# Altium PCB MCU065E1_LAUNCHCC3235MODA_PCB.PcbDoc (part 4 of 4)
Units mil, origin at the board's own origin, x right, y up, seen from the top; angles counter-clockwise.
Board outline 2300 x 4280 mil, 4 copper layers (TOP, GND, PWR, BOTTOM), stack 62 mil thick; 300 components, 199 nets, 970 pads, 475 vias.
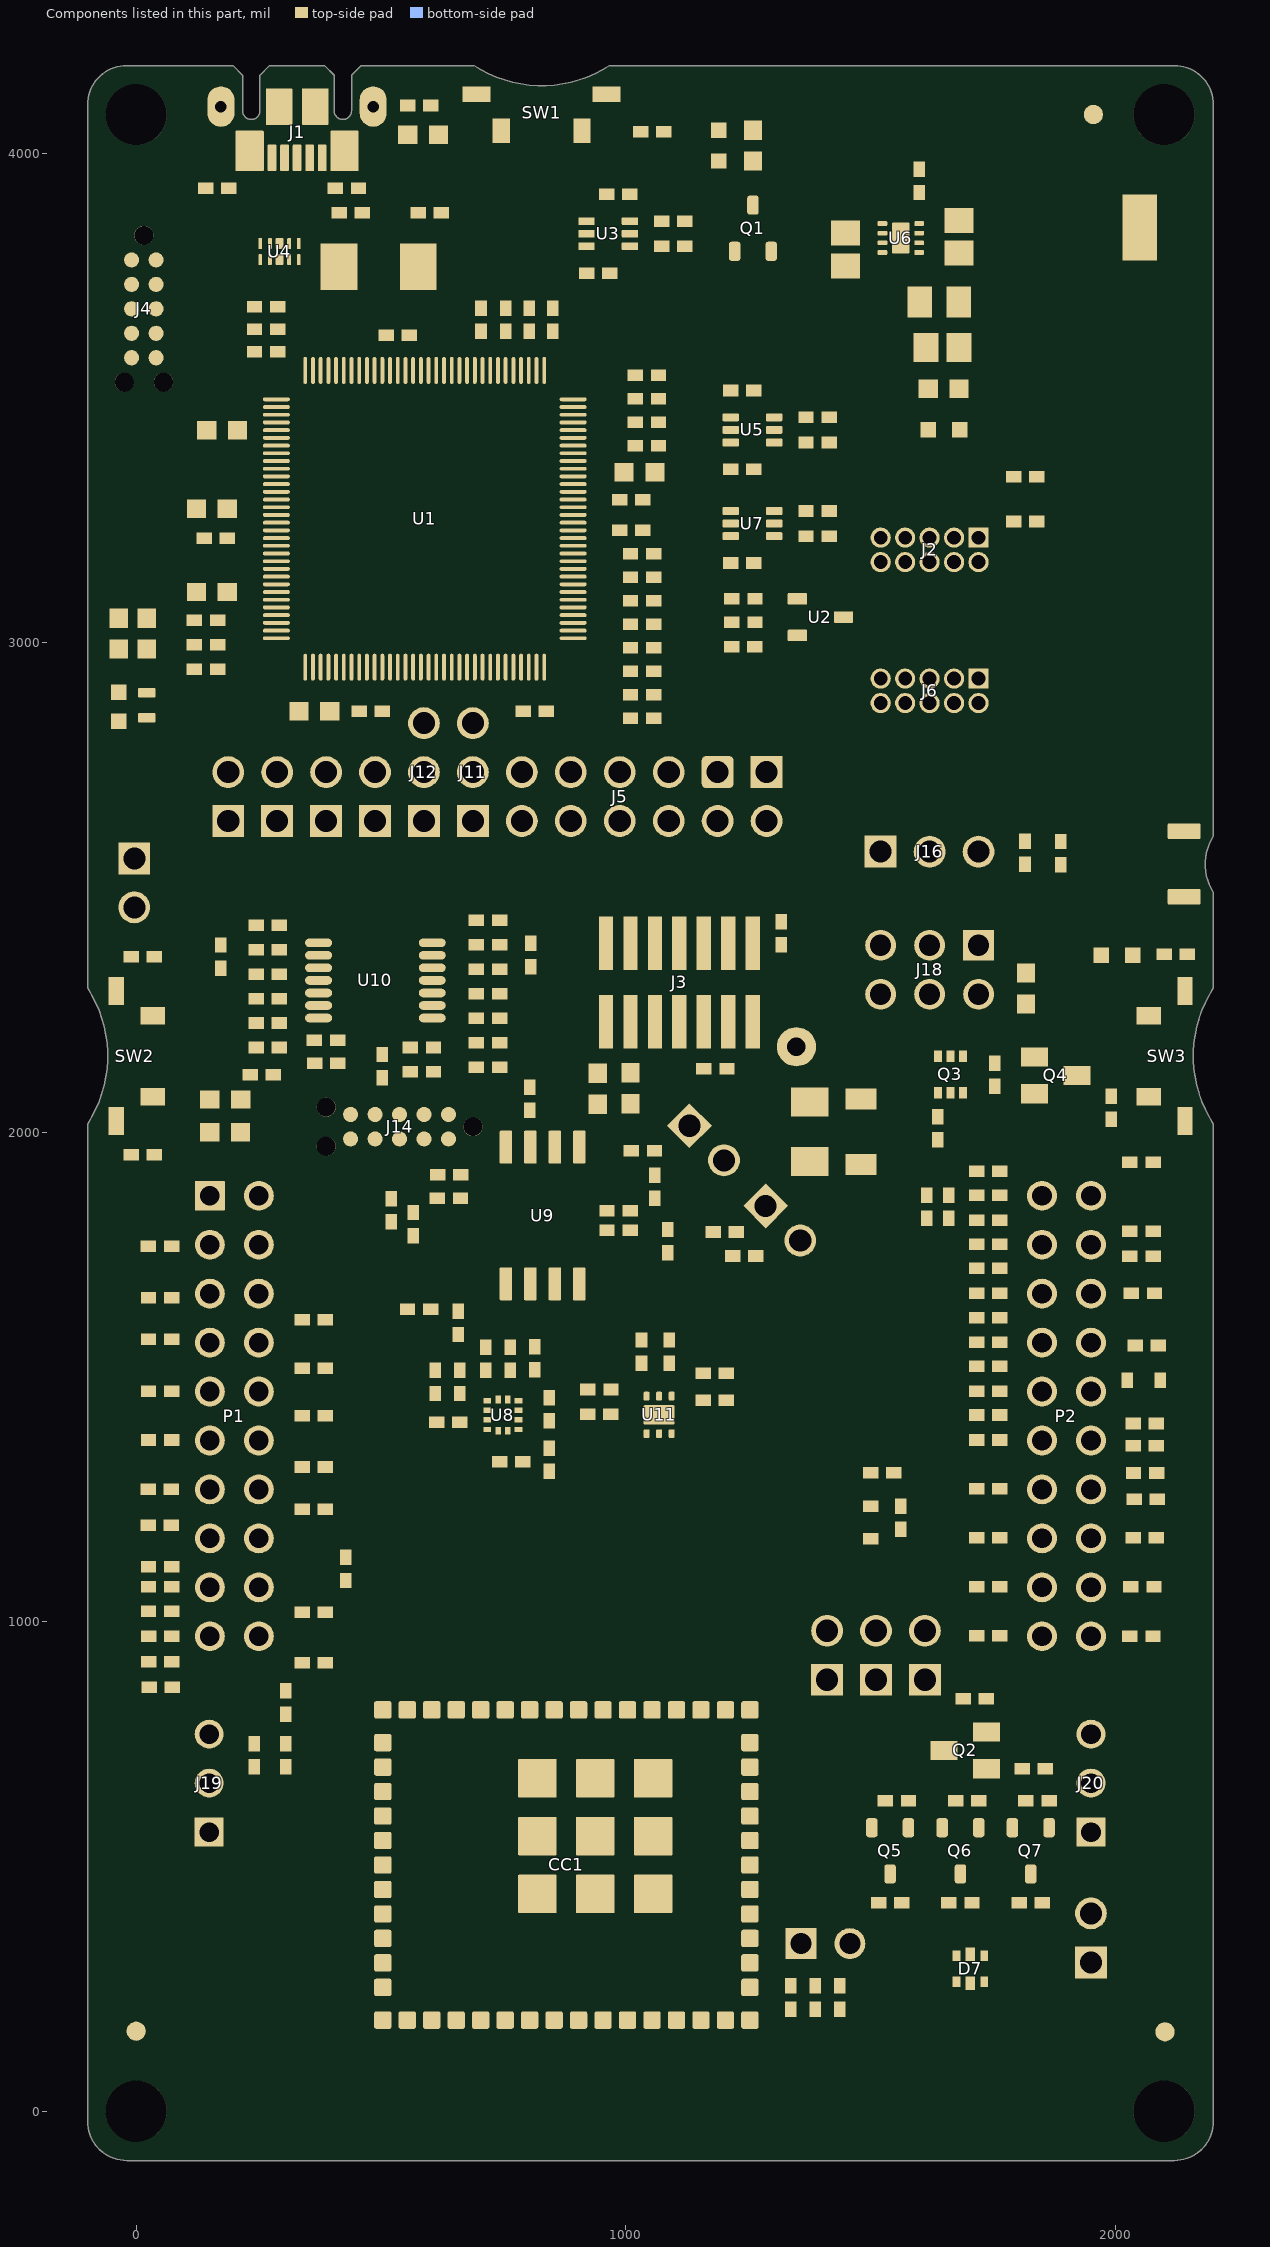
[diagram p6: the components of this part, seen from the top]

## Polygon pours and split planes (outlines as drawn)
no net on M4 3D STEP Bottom "M4 3D STEP Bottom-No Net" (solid, pour order 341): 2155.79,401.26 ccw(c2095.79,401.26) 2095.79,461.26 ccw(c2095.79,401.26) 2035.79,401.26 ccw(c2095.79,401.26) 2095.79,341.26 ccw(c2095.79,401.26) 2155.79,401.26
no net on M4 3D STEP Bottom "M4 3D STEP Bottom-No Net" (solid, pour order 342): 60.79,366.26 ccw(c0.79,366.26) 0.79,426.26 ccw(c0.79,366.26) -59.21,366.26 ccw(c0.79,366.26) 0.79,306.26 ccw(c0.79,366.26) 60.79,366.26
no net on M4 3D STEP Bottom "M4 3D STEP Bottom-No Net" (solid, pour order 340): 2015.79,3726.26 ccw(c1955.79,3726.26) 1955.79,3786.26 ccw(c1955.79,3726.26) 1895.79,3726.26 ccw(c1955.79,3726.26) 1955.79,3666.26 ccw(c1955.79,3726.26) 2015.79,3726.26
GND on TOP "GND_L01_P327" (solid, remove dead copper, pour order 327): -99.1,-100.74 2203.8,-100.74 2203.8,4117.38 2138.8,4182.38 -47.5,4182.38 -99.1,4130.78
VBUS_USB1 on TOP "L3 Signal-No Net" (solid, pour order 325): 1534.45,3807.43 1391.7,3807.43 1378.25,3820.88 1378.25,3883.02 1398.45,3903.22 1480.79,3903.22 1490.45,3893.57 1490.45,3851.56 1495.39,3846.61 1537.4,3846.61 1541.12,3842.89 1541.12,3814.11
VCC_LDO_3V3 on TOP "L3 Signal-No Net" (solid, remove dead copper, pour order 326): 1669.88,3489.43 1728.7,3489.43 1751.99,3512.73 1751.99,3810.28 1735.84,3826.44 1615.61,3826.44 1612.61,3823.43 1612.61,3799.01 1654.29,3757.33 1654.29,3505.03
GND on BOTTOM "GND_L04_P339" (solid, remove dead copper, pour order 339): -99.1,-100.74 2203.8,-100.74 2203.8,4117.38 2138.8,4182.38 -47.5,4182.38 -97.5,4132.38 -97.5,4124.08 -99.1,4132.38
VCC_BRD on BOTTOM "VCC_BRD_L04_P337" (solid, remove dead copper, pour order 337): 2057.55,2644.15 2088.64,2675.25 2088.64,3228.53 1920.48,3396.7 1837.19,3396.7 1812.21,3396.7 1790.73,3375.22 1790.73,3177.95 1881.36,3087.32 1881.36,2987.13 1720.25,2826.02 1389,2826.02 1232.05,2669.06 1232.05,2551.64 1326.07,2457.61 1871.01,2457.61
VBUS_USB1 on BOTTOM "VBUS_USB1_L04_P338" (solid, remove dead copper, pour order 338): 51.88,2994.75 70.47,2976.16 125.75,2976.16 229.68,2872.23 229.68,2698.8 247.53,2680.94 406.96,2680.94 406.96,2683.58 439.86,2716.48 439.86,2904.48 406.96,2937.38 406.96,3312.96 527.47,3433.47 846.63,3433.48 1109.11,3695.97 1376.48,3695.97 1493.72,3813.21 1493.72,3918.79 1368.78,4043.73 1163.57,4043.73 1107.39,3987.54 606.61,3987.54 128.57,3987.54 79,3937.98 79,3746.2 172.95,3652.26 172.95,3503.67 51.88,3382.6
VCC_LDO_3V3 on PWR "PWR-No Net 3" (solid, remove dead copper, pour order 336): -99.21,4188.01 2200.79,4188.01 2200.79,2650.8 -99.21,2650.8
VCC_BRD on PWR "PWR-No Net 2" (solid, remove dead copper, pour order 335): -70.85,2651.9 384.52,2651.9 378.6,2329.9 253,2204.3 253,1970.21 1429,1677.24 1429,1234.2 1409.8,978.7 1409.8,711.6 1409.8,608.7 1107.3,306.2 -96.59,306.2 -100.43,1408.72 -99.21,1708.3 -70.85,1825.15
VBAT_CC on PWR "PWR-No Net 1" (solid, remove dead copper, pour order 334): 1049.92,1711.49 1049.93,1768.6 1015.38,1803.15 237.06,2010.16 237.06,2668.65 1542.9,2668.64 1856.72,2297.02 1856.72,438.3 1674.62,438.3 1654.56,293.87 1388.14,272.26 1397.77,595.55 1419.98,1341.44
GND on PWR "GND_L03_P332" (solid, remove dead copper, pour order 332): 431.08,524.74 572.16,524.74 777.95,730.53 1403.16,730.53 1403.16,289.92 1649.27,289.92 1661.9,-81.9 1664.1,-84.1 1647.46,-100.74 -103.82,-100.74 -92.13,326.1 227.01,320.67
VCC_BRD on PWR "VCC_BRD_L03_P333" (solid, remove dead copper, pour order 333): 1614.61,1945.17 1598.72,1945.17 1575.31,1968.59 1575.31,2002.44 1614.61,2041.74 1614.61,2606.59 1572.12,2649.08 1472.7,2649.08 1342.43,2518.81 582.21,2518.82 536.84,2564.19 536.84,2669.42 528.87,2677.39 433.73,2677.39 403.3,2646.96 403.3,2461.78 384.05,2442.53 -70.59,2434.92 -70.59,2796.96 2200.79,2796.96 2200.79,1257.1 1865.7,1257.1 1865.7,1738.81 1614.61,1944.64
GND on PWR "GND_L03_P330" (solid, remove dead copper, pour order 330): 2107.5,1195.1 2061.5,1257.2 1856.4,1269.2 1856.4,565.53 1733.27,442.4 1684.9,442.4 1667,424.4 1500.1,257.5 1500.1,-96.92 1776.99,-79.41 1786.17,-6.81 1989.6,165.08 1989.6,286.1 2072.85,369.35 2107.5,896.54
VCC_BRD on PWR "VCC_BRD_L03_P329" (solid, remove dead copper, pour order 329): 1656.35,163.28 1656.35,237.76 1758.3,339.7 1808.45,339.7 2067.6,598.84 2067.6,1280.1 2056.8,1290.9 2203.8,1291.9 2203.8,-75.9 2207.8,-79.9 2204.8,-82.9 1656.34,-82.9
VCC_BUFFER on PWR "L3 Signal-No Net" (solid, remove dead copper, pour order 331): 1323.98,2943.63 1235.06,2854.7 1235.06,2815.65 1263.98,2786.73 1381.62,2786.73 1483.34,2888.45 1483.34,2939.26 1516.43,2972.35 1664.3,2972.35 1730.31,2972.35 1838.04,3080.09 1838.04,3168.38 1808.5,3197.92 1808.5,3283.36 1570.69,3521.17 1570.69,3766.03 1373.14,3963.58 1163.65,3963.58 1033.35,3833.28 1033.35,3673.64 1153.72,3553.27 1153.72,3421.02 1189.35,3385.38 1272.5,3385.38 1323.98,3333.91
GND on GND "GND_L02_P328" (solid, remove dead copper, pour order 328): -99.1,-100.74 2203.8,-100.74 2203.8,4117.38 2138.8,4182.38 -47.5,4182.38 -97.5,4132.38 -97.5,4124.08 -99.1,4132.38

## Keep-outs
Keep-Out Layer:
  circle w1: c15.79,3832.26 r32
  circle w1: c55.79,3532.26 r30
  circle w1: c-24.21,3532.26 r30
  circle w1: c0,163.48 r60
  circle w1: c2101.9,162.18 r60
  circle w1: c2101.57,-1.52 r79.5
  circle w1: c388.2,1971.38 r30
  circle w1: c388.2,2051.38 r30
  circle w1: c688.2,2011.38 r32
  circle w1: c0,-1.52 r79.5
  circle w1: c1955.64,4079.33 r60
  lines w1: 222.28,-97.58 222.28,-83 -20,-83 cw(c-20,-20) -83,-20 -83,2017.29 -82.21,2018.08 ccw(c-302.14,2156.76) -82.21,2295.45 -83,2296.24 -83,4098.53 cw(c-20,4098.53) -20,4161.53 197.88,4161.53 207.57,4151.84 207.57,4069.01 ccw(c235.28,4081.93) 263,4069.01 263,4151.84 272.68,4161.53 384.89,4161.53 394.57,4151.84 394.57,4069.01 ccw(c422.29,4081.93) 450.01,4069.01 450.01,4151.84 459.69,4161.53 689.5,4161.53 ccw(c828.09,4381.51) 966.75,4161.57 ; 780.99,-97.58 780.99,-83 2120,-83 ccw(c2120,-20) 2183,-20 2183,2017.26 ; 966.77,4161.53 2120,4161.53 ; 1383.58,4161.53 2120,4161.53 ; 2183.06,2017.26 cw(c2402.98,2155.95) 2183,2294.54 2182.99,2483.26 2121,2483.26 2121,2611.26 2183,2611.26 2183,4098.53 ccw(c2120,4098.53) 2120,4161.53

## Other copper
TOP:
  pour cut-out: 622.3,144.68 618.71,136.98 691.76,136.98 686.21,144.68
  pour cut-out: 173.93,3405.65 177.55,3405.65 179.55,3407.65 179.55,3461.05 177.55,3463.05 173.93,3463.05
  pour cut-out: 153.05,3302.19 156.68,3302.19 158.68,3300.19 158.68,3246.79 156.68,3244.79 153.05,3244.79
  pour cut-out: 153.05,3132.34 156.68,3132.34 158.68,3130.34 158.68,3076.94 156.68,3074.94 153.05,3074.94
  pour cut-out: 45.42,2881.04 45.42,2863.58 -61.23,2863.58 -61.23,2875.14 -20.37,2875.14 -14.47,2881.04
  pour cut-out: 361.88,2831.4 368.81,2831.4 368.81,2879.59 361.88,2879.59
  pour cut-out: 50.37,3020.34 -63.83,3020.34 -63.83,3016.37 -62.18,3014.72 48.37,3014.72 50.37,3016.72
  pour cut-out: -99.21,136.98 2200.79,136.98 2200.79,-99.62 -99.21,-99.62
  pour cut-out: 686.21,236.99 686.21,144.68 621.66,144.68 621.66,236.91
  text ".layer_Name" at -465.21,-1154.21 h60
GND:
  pour cut-out: 979.65,2784.19 979.65,2773.17 981.26,2771.56 993.17,2771.56 994.18,2772.57 994.18,2783.18 991.44,2785.92 981.38,2785.92
  pour cut-out: 1096.58,3469.94 1096.58,3529.33 1099.49,3532.25 1105.33,3532.25 1108.41,3529.17 1108.41,3469.16 1105.79,3466.54 1099.98,3466.54
  pour cut-out: -99.21,136.98 2200.79,136.98 2200.79,-99.62 -99.21,-99.62
  text ".layer_Name" at -465.21,-1154.21 h60
PWR:
  pour cut-out: 355.99,2432.31 355.99,2413.97 363.04,2413.97 364.21,2415.14 364.21,2431.11 363.01,2432.31
  pour cut-out: -99.21,136.98 2200.79,136.98 2200.79,-99.62 -99.21,-99.62
  text ".layer_Name" at -465.21,-1154.21 h60
BOTTOM:
  region net SOP0: 788.75,257.91
  pour cut-out: 1096.58,3469.94 1096.58,3529.33 1099.49,3532.25 1105.33,3532.25 1108.41,3529.17 1108.41,3469.16 1105.79,3466.54 1099.98,3466.54
  pour cut-out: 773.96,3727.62 833.35,3727.62 836.26,3724.7 836.26,3718.87 833.18,3715.79 773.17,3715.79 770.55,3718.41 770.55,3724.22
  pour cut-out: 1080.79,3131.86 1080.79,3111.42 1088.9,3103.31 1120.32,3103.31 1126.68,3109.66 1126.68,3139.18 1120.05,3145.81 1094.74,3145.81
  pour cut-out: -99.21,136.98 2200.79,136.98 2200.79,-99.62 -99.21,-99.62
  text ".layer_Name" at -465.21,-1154.21 h60

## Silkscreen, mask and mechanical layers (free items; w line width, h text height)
SILKSCREEN TOP:
  drawing of 4383 lines, arcs and shapes, not listed
  text "RESET" at 1150.16,3967.53 h30 r90
  text "RESET" at 766.83,3936.04 h30
  text "3V3" at 1740.67,3461.56 h30
  text "XDS110 / OUT" at 1537.41,3298.92 h30
  text "'.PRJ_Number''.PCB_Rev'" at 2157.66,3232.13 h30 r90
  text "JTAG IN" at 1522.52,3024.17 h30
  text "VBuffer" at 1303.04,2812.01 h30 r90
  text "PCB Rev. .PCB_Rev" at 2157.27,2808.83 h30 r90
  text "XDS110 Debug Probe" at 1423.97,2718.77 h40
  text "SOP Pull-Up" at 1483,2569.76 h50
  text "TX" at 707.95,2516.25 h30 r90
  text "RX" at 603.59,2513.11 h30 r90
  text "5V" at 404.75,2510.26 h30 r90
  text "TDI" at 1202.52,2509.54 h30 r90
  text "BRD" at 203.68,2486.4 h30 r90
  text "RST" at 802.45,2486.4 h30 r90
  text "TCK" at 1004.45,2486.4 h30 r90
  text "TDO" at 1102.5,2486.69 h30 r90
  text "BRD" at 1305.29,2486.4 h30 r90
  text "TMS" at 904.43,2484.83 h30 r90
  text "GND" at 310.28,2483.26 h30 r90
  text "VBAT" at 505.16,2456.55 h30 r90
  text "VCC_BRD" at 1747.18,2455.56 h22
  text "VBAT_CC" at 1348.04,2445.25 h22
  text "FRST" at 1953.1,2400.78 h25
  text "OPAMP EN" at 102.12,2400.14 h30 r90
  text "ET POD" at 906,2290 h30 r90
  text "SOP" at 1457.77,2282.91 h40 r90
  text "0" at 1734.86,2217.75 h25 r180
  text "2" at 1513.93,2191.38 h25
  text "1" at 1617.53,2190.64 h25
  text "(P15)" at 1946.23,2149 h25
  text "(P04)" at 74.2,2147.87 h25
  text "P1" at 81.01,1922.43 h30
  text "P3" at 278.51,1921.74 h30
  text "21" at 213.8,1920.78 h25
  text "1" at 164.5,1920.08 h25
  text "*" at 1665.99,1918.54 h30
  text "P02" at 1596.39,1907.16 h25
  text "*" at -19.41,1782.22 h25
  text "*" at 1661.46,1758.72 h30
  text "P58" at -83.45,1756.97 h25
  text "P01" at 1596.39,1755.68 h25
  text "P18" at 2120.33,1755.68 h25
  text "SDA" at 1200,1683 h30
  text "*" at 1664.92,1667.49 h30
  text "P04" at -83.45,1659.65 h25
  text "P57" at 328.8,1659.65 h25
  text "P17" at 1596.39,1655.55 h25
  text "P08" at 2120.33,1655.55 h25
  text "SCL" at 1203,1619 h30
  text "*" at 1661.46,1566.25 h30
  text "P03" at -83.45,1560.47 h25
  text "P60" at 328.8,1560.47 h25
  text "P64" at 1596.39,1553.52 h25
  text "*" at 1661.46,1470.67 h30
  text "RST" at 2170.6,1459.76 h25 r90
  text "P61" at -83.45,1458 h25
  text "P58" at 328.8,1458 h25
  text "P21" at 1605.88,1453.55 h25
  text "*" at 1666.24,1384.42 h30
  text "*" at -21.47,1384.18 h25
  text "P18" at 1610.14,1363.77 h25
  text "P07" at 2120.33,1363.59 h25
  text "P59" at -83.45,1357 h25
  text "P59" at 328.8,1357 h25
  text "SENSORS" at 1033.99,1278.98 h30
  text "P05" at -83.45,1260 h25
  text "P63" at 328.8,1260 h25
  text "P06" at 2120.33,1257.45 h25
  text "P62" at 1603.37,1256.22 h25
  text "P62" at -83.45,1161.46 h25
  text "P53" at 328.8,1161.46 h25
  text "P21" at 2120.33,1160.88 h25
  text "P60" at 1605.76,1157.51 h25
  text "P16" at 1612.22,1060.51 h25
  text "P01" at -83.45,1060 h25
  text "P64" at 328.8,1060 h25
  text "P55" at 2120.33,1058.16 h25
  text "P17" at 1714.47,1005.12 h25
  text "P02" at -83.45,958.83 h25
  text "P50" at 328.8,958.83 h25
  text "P15" at 2120.33,958.79 h25
  text "RST PU" at 1314.92,409.43 h30
  text "SILKSCREEN TOP" at -467.21,-1156.21 h60
SILKSCREEN BOTTOM:
  drawing of 4377 lines, arcs and shapes, not listed
  text "CC3235MODA" at 1190.68,3701.27 h72.83
  text "LaunchPad™ Development kit" at 1176.7,3591.28 h72.83
  text "www.ti.com/launchpad" at 1547.59,3328.68 h100
  text "SOP (2:0)" at 2150.61,3322.14 h45
  text "100  :  FLASH" at 2150.74,3270.07 h45
  text "000  :  4W JTAG" at 2150.94,3211.07 h45
  text "001  :  2W SWD" at 2152.14,3158.07 h45
  text "010  :  FLASH/FUNC" at 2151.54,3105.35 h45
  text "XDS110 OUT" at 1755.5,2980.65 h45
  text "VBuffer" at 1264.94,2770.21 h45 r270
  text "JTAG IN" at 1753.7,2710.98 h45
  text "SOP Pull-Up" at 1766.75,2569.72 h50
  text "TX" at 671.92,2516.47 h30 r270
  text "RX" at 572.01,2513.32 h30 r270
  text "5V" at 375.13,2510.47 h30 r270
  text "TDI" at 1174.05,2509.75 h30 r270
  text "BRD" at 174.08,2486.62 h30 r270
  text "RST" at 773.45,2486.62 h30 r270
  text "TCK" at 972.29,2486.62 h30 r270
  text "TDO" at 1073.82,2486.9 h30 r270
  text "BRD" at 1274.61,2486.62 h30 r270
  text "TMS" at 872.06,2485.04 h30 r270
  text "GND" at 273.27,2483.47 h30 r270
  text "VBAT" at 472.11,2456.76 h30 r270
  text "SOP" at 1664.7,2440.48 h40
  text "OPAMP EN" at 76.43,2402.2 h30 r270
  text "SDA" at 1240.93,1991.85 h30 r315
  text "P4" at 1801.53,1963.4 h30
  text "P1" at 118.17,1962.24 h30
  text "P3" at 330.03,1962.24 h30
  text "P2" at 2030.03,1962.25 h30
  text "1" at 167,1948.48 h35
  text "21" at 266,1948.48 h35
  text "40" at 1878,1948.48 h35
  text "20" at 1969,1948.48 h35
  text "P02" at 1777.79,1853.26 h35
  text "SCL" at 1390.49,1834.86 h30 r315
  text "P01" at 1777.79,1758.26 h35
  text "P18" at 2098.45,1758.26 h35
  text "P58" at 80,1750.88 h31
  text "P17" at 1777.79,1656.26 h35
  text "P08" at 2098.45,1656.26 h35
  text "P04" at 80,1652.88 h35
  text "P57" at 399.7,1652.88 h35
  text "P03" at 80,1562.18 h35
  text "P60" at 399.7,1562.18 h35
  text "P64" at 1777.79,1555.26 h35
  text "P45" at 2098.45,1555.26 h35
  text "P61" at 80,1464.58 h35
  text "P58" at 399.7,1464.58 h35
  text "P21" at 1777.79,1455.26 h35
  text "RST" at 2098.45,1455.26 h35
  text "P18" at 1777.79,1357.88 h35
  text "P07" at 2098.45,1357.88 h35
  text "P59" at 80,1355.98 h33
  text "P59" at 399.7,1353.98 h35
  text "P62" at 1777.79,1257.26 h35
  text "P06" at 2098.45,1257.26 h35
  text "P05" at 80,1248.26 h35
  text "P63" at 399.7,1248.26 h35
  text "P60" at 1777.79,1155.26 h35
  text "P21" at 2098.45,1155.26 h35
  text "P62" at 80,1140.28 h35
  text "P53" at 399.7,1140.28 h35
  text "P16" at 1777.79,1055.26 h35
  text "P55" at 2098.45,1055.26 h35
  text "P01" at 80,1048.26 h35
  text "P64" at 399.7,1048.26 h35
  text "P17" at 1777.79,955.26 h35
  text "P15" at 2098.45,955.26 h35
  text "P02" at 80,948.26 h35
  text "P50" at 399.7,948.26 h35
  text "30" at 269.16,856.26 h35
  text "31" at 1869.3,855.48 h35
  text "11" at 1963.2,856.28 h35
  text "10" at 166.39,854.26 h35
  text "RST PU" at 1462.89,409.46 h30
  text "SILKSCREEN BOTTOM" at -465.6,-1156.9 h60
Top Paste:
  text ".layer_Name" at -467.21,-1136.22 h60
Top Solder:
  text ".layer_Name" at -467.21,-1136.22 h60
Bottom Solder:
  text ".layer_Name" at -467.21,-1156.21 h60
M1  Board Outline:
  the board outline again, w10
  text "BOARD OUTLINE" at -463.74,-1156.53 h60
M2 Board Dimensions:
  circle w4: c324.86,4114.66 r192.32
  lines w10: 198.74,5584.51 689.56,5584.51 ; 314.19,5362.14 333.87,5342.46 333.87,5269.62 ccw(c351.59,5269.62) 369.3,5269.62 369.31,5342.46 388.99,5362.14 501.19,5362.14 520.88,5342.46 520.88,5269.62 ccw(c538.6,5269.62) 556.31,5269.62 ; 556.31,5269.62 556.31,5342.46 576,5362.14 ; -112.42,4824.91 960.17,4824.91 960.17,5749.43 -112.42,5749.43 -112.42,4824.91
  text "DETAIL A" at 224.79,5613.3 h60
  text "BOARD DIMENSIONS" at -465.55,-1160.15 h60
M4 3D STEP Bottom:
  text "This is the universal DXF file that is provided to Customers," at 3178.55,-588.85 h23.58
AST:
  circle w6: c78.79,567.26 r10
  circle w6: c78.79,567.26 r10
  region: 1328.27,1897.45 1302.72,1923 1293,1913.28 1318.55,1887.74
  region: 1172.47,2061.15 1146.92,2086.7 1137.2,2076.98 1162.75,2051.44
  rectangle: 1282.19,2785.86 1318.32,2799.61
  region: 1713.23,523.69 1713.23,487.56 1726.97,487.56 1726.97,523.69
  rectangle: -9.51,2609.28 26.61,2623.02
  region: 388.93,3785.89 388.93,3822.02 375.19,3822.02 375.19,3785.89
  region: 1641.81,831.5 1605.69,831.5 1605.69,817.76 1641.81,817.76
  region: 1541.81,831.5 1505.69,831.5 1505.69,817.76 1541.81,817.76
  region: 1441.81,831.5 1405.69,831.5 1405.69,817.76 1441.81,817.76
  region: 1295.28,381.8 1295.28,345.67 1309.03,345.67 1309.03,381.8
  region: 1735.85,278.97 1735.85,259.7 1743.88,259.7 1743.88,278.97
  region: 1756.75,3221.23 1756.75,3257.36 1743,3257.36 1743,3221.23
  region: 1756.75,2933.23 1756.75,2969.36 1743,2969.36 1743,2933.23
  region: 1471,2567.44 1471,2603.57 1457.26,2603.57 1457.26,2567.44
  rectangle: 1192.03,2785.86 1228.16,2799.61
  rectangle: 682.19,2572.12 718.31,2585.86
  rectangle: 582.19,2572.12 618.31,2585.86
  rectangle: 482.19,2572.12 518.31,2585.86
  rectangle: 382.19,2572.12 418.31,2585.86
  rectangle: 282.19,2572.12 318.31,2585.86
  rectangle: 182.19,2572.12 218.31,2585.86
  lines w10: -1273.71,-1222.38 5326.29,-1222.38 ; -1273.71,-1019.05 5328.29,-1019.05 ; -1273.71,-815.71 -1273.71,-1425.71 2731.29,-1425.71 5328.29,-1425.71 5328.29,-815.71 -1273.21,-815.71 -1273.21,-1425.71 302.29,-1425.71 ; 1191.29,-1425.71 1191.29,-815.71 ; 2458.29,-1019.05 2458.29,-815.71 ; 3298.29,-1019.05 3298.29,-815.71 ; 3920.29,-1432.21 3920.29,-1229.38
  text "COMPONENTS MARKED 'DNP' SHOULD NOT BE POPULATED." at 171.79,-610.71 h35
  text "ASSEMBLY VARIANT:" at 171.29,-726.21 h35
  text ".VariantName" at 1207.29,-726.21 h35
  text "PCB VIEWED FROM TOP SIDE" at -1210.21,-947.88 h35
  text "BOARD #:" at 1266.29,-947.88 h35
  text ".PRJ_Number" at 1811.79,-947.88 h35
  text "REV:" at 2656.29,-947.88 h35
  text ".PCB_Rev" at 2947.79,-947.88 h35
  text "SVN REV:" at 3494.29,-947.88 h35
  text ".VersionControl_RevNumber" at 4000.29,-947.88 h35
  text "TOP ASSEMBLY DRAWING" at -1210.21,-1150.71 h35
  text "GENERATED    :" at 1268.29,-1356.55 h35
  text ".Print_Date" at 2137.79,-1356.55 h35
  text ".Print_Time" at 2866.79,-1356.55 h35
  text "TEXAS INSTRUMENTS" at 4131.29,-1356.55 h35
ASB:
  lines w10: -1274.21,-1019.55 5327.79,-1019.55 ; -1272.21,-1222.88 5327.79,-1222.88 ; 133.79,-1432.71 133.79,-1229.88 ; 755.79,-1019.55 755.79,-816.21 ; 1595.79,-1019.55 1595.79,-816.21 ; 2862.79,-1426.21 2862.79,-816.21 ; 3751.79,-1426.21 5327.29,-1426.21 5327.29,-816.21 -1274.21,-816.21 -1274.21,-1426.21 1322.79,-1426.21 5327.79,-1426.21 5327.79,-816.21
  text "COMPONENTS MARKED 'DNP' SHOULD NOT BE POPULATED." at 5120.29,-610.21 h35
  text ".VariantName" at 4076.29,-726.21 h35
  text "ASSEMBLY VARIANT:" at 5115.29,-726.21 h35
  text ".VersionControl_RevNumber" at 53.79,-948.38 h35
  text "SVN REV:" at 559.79,-948.38 h35
  text ".PCB_Rev" at 1106.29,-948.38 h35
  text "REV:" at 1397.79,-948.38 h35
  text ".PRJ_Number" at 2242.29,-948.38 h35
  text "BOARD #:" at 2787.79,-948.38 h35
  text "PCB VIEWED FROM BOTTOM SIDE" at 5264.29,-948.38 h35
  text "BOTTOM ASSEMBLY DRAWING" at 5264.29,-1152.71 h35
  text "TEXAS INSTRUMENTS" at -77.21,-1357.05 h35
  text ".Print_Time" at 1187.29,-1357.05 h35
  text ".Print_Date" at 1916.29,-1357.05 h35
  text "GENERATED    :" at 2785.79,-1357.05 h35
M9 Title Sheet:
  drawing of 56 lines, arcs and shapes, not listed
  text "1" at -252.91,7735.73 h70
  text "2" at 2242.75,7735.73 h70
  text "3" at 4732.1,7735.73 h70
  text "4" at 7238.77,7735.73 h70
  text "5" at 9737.75,7735.73 h70
  text "6" at 12242.75,7735.73 h70
  text "A" at -1409.25,6592.73 h70
  text "A" at 13390.75,6592.73 h70
  text "B" at -1409.25,4212.73 h70
  text "B" at 13390.75,4212.73 h70
  text "C" at -1409.25,1837.73 h70
  text "C" at 13390.75,1837.73 h70
  text "PROJECT TITLE:" at 10350.75,-23.27 h45
  text ".PRJ_Title" at 10400.75,-156.6 h70
  text "DESIGNED FOR:" at 10350.75,-324.27 h45
  text ".PRJ_Customer" at 10400.75,-464.27 h70
  text "D" at -1409.25,-532.27 h70
  text "D" at 13390.75,-532.27 h70
  text "FILE NAME:" at 10350.75,-624.27 h45
  text ".PCB_File_Name_No_Path" at 10400.75,-744.27 h70
  text "Texas Instruments (TI) and/or its licensors do not warrant the accuracy or completeness of this specification" at 5381.25,-906.11 h45
  text "ENGINEER:" at 10350.75,-914.27 h45
  text "LAYOUT BY:" at 11855.75,-914.27 h45
  text "or any information contained therein. TI and/or its licensors do not warrant that this design will meet" at 5336.27,-1018.77 h45
  text ".PRJ_Engineer" at 10400.75,-1069.26 h70
  text ".PCB_Layout" at 11906.25,-1069.26 h70
  text "the specifications, will be suitable for your application or fit for any particular purpose, or will operate in" at 5336.27,-1131.44 h45
  text "ALTIUM DESIGNER VERSION:" at 11855.75,-1224.27 h45
  text "an implementation. TI and/or its licensors do not warrant that the design is production worthy. You should" at 5336.27,-1244.1 h45
  text "completely validate and test your design implementation to confirm the system functionality for your application." at 5381.25,-1356.77 h45
  text ".print_Scale" at 10400.75,-1357.6 h70
  text ".Application_BuildNumber" at 11906.25,-1357.6 h70
  text "1" at -252.91,-1564.27 h70
  text "2" at 2242.75,-1564.27 h70
  text "3" at 4732.1,-1564.27 h70
  text "4" at 7238.77,-1564.27 h70
  text "5" at 9737.75,-1564.27 h70
  text "WO # : 307464-7462-D" at 12242.75,-1564.27 h70
M10 Fab Notes:
  drawing of 201 lines, arcs and shapes, not listed
  text "ADDITIONAL NOTE :" at -978.48,7127.45 h100
  text "THE SOLDER MASK IMAGES THAT ARE THE SAME SIZE AS THE COMPONENT PADS MAY BE ENLARGED AS PER THE MANUFACTURING CAPABILITIES" at -794.46,6900.05 h100
  text "BUT NOT BEYOND 0.08MM PER SIDE OR 0.15MM OVERALL. ALL OTHER SOLDER MASK IMAGES SHALL NOT BE MODIFIED." at -794.46,6738.09 h100
  text "DESIGN INFORMATION" at 11388.27,6144.23 h60
  text "MIN. TRACK WIDTH:" at 10743.71,5964.23 h60
  text "MIL" at 11994.71,5964.23 h60
  text "6" at 11835.79,5962.79 h60
  text "5" at 11841.45,5835.24 h60
  text "MIN. CLEARANCE:" at 10743.71,5832.23 h60
  text "MIL" at 11994.71,5832.23 h60
  text "19.7" at 11756.98,5701.36 h60
  text "MIN. VIA PAD SIZE:" at 10743.71,5700.23 h60
  text "MIL" at 11994.71,5700.23 h60
  text "0.05mm (2MIL)" at 11510.95,5563.21 h60
  text "EXTERNAL" at 12289,5560 h60
  text "MINIMUM ANNULAR RING" at 10414.48,5554.23 h60
  text "PER" at 10614.48,5436.23 h60
  text "IPC-D-275 CLASS 2 LEVEL C" at 10834.48,5436.23 h60
  text "MIL, HOLES" at 12322.71,5323.94 h60
  text "+/-" at 11930.25,5323.23 h60
  text "+/-" at 12784.25,5323.23 h60
  text "REGISTRATION TOLERANCES:" at 10414.48,5318.23 h60
  text "METAL" at 11614.25,5318.23 h60
  text "5" at 12190.46,5318.23 h60
  text "3" at 13023.46,5318.23 h60
  text "MIL" at 13139.71,5318.23 h60
  text "MATERIAL:" at 10339.71,5108.77 h60
  text "FR-4 High Tg" at 11326.16,4968.44 h60
  text "FR-408" at 10760.72,4959.87 h60
  text "OTHER" at 12248.71,4959.87 h60
  text "X" at 12066.51,4945.48 h60
  text "FR-4 High TG / Halogen-Free" at 12606.06,4893.62 h60
  text "1.4mm+/-10%" at 12612.25,4799.23 h60
  text "62 MIL (1.6mm) +/-10%" at 11080.82,4797.15 h60
  text "THICKNESS:" at 10414.48,4792.87 h60
  text "X" at 10949.25,4792.87 h60
  text "OTHER" at 12345.71,4792.87 h60
  text "TOLERANCE:" at 10414.48,4634.87 h60
  text "X" at 11253.79,4634.87 h60
  text "ANSI IPC-6012 TYPE 3 CLASS 2" at 11440.73,4634.87 h60
  text "OTHER +/-" at 11440.71,4478.87 h60
  text "BOW & TWIST:" at 10414.48,4321.87 h60
  text "X" at 11253.79,4321.87 h60
  text "ANSI IPC-6012 TYPE 3 CLASS 2" at 11440.73,4321.87 h60
  text "OTHER +/-" at 11440.71,4163.36 h60
  text "COPPER THICKNESS (FINISHED):" at 10393.25,3906.93 h60
  text "1.4MIL (1oz)" at 12645.25,3759.21 h60
  text "INNER SIGNAL:" at 11833.17,3754.93 h60
  text "X" at 12518.21,3754.93 h60
  text "1.4MIL (1oz)" at 11273.25,3754.21 h60
  text "OUTER:" at 10750.25,3749.93 h60
  text "X" at 11144.79,3749.29 h60
  text "DRILLING:" at 10339.71,3489.87 h60
  text "REFERENCE:" at 10414.48,3372.87 h60
  text "X" at 11062.71,3372.87 h60
  text "AS SHOWN" at 11249.71,3372.87 h60
  text "X" at 11963.71,3372.87 h60
  text "NC_DRILL FILES" at 12100.71,3372.87 h60
  text "PTH MIN COPPER THICKNESS:" at 10414.48,3214.87 h60
  text "X" at 11764.71,3214.87 h60
  text "1MIL" at 11901.71,3214.87 h60
  text "OTHER" at 12398.71,3214.87 h60
  text "BOARD FINISH:" at 10339.71,3055.87 h60
  text "SILKSCREEN:" at 10494.94,2937.87 h60
  text "X" at 11443.71,2937.87 h60
  text "TOP" at 11569.71,2937.87 h60
  text "X" at 11953.71,2937.87 h60
  text "BOTTOM" at 12080.71,2937.87 h60
  text "SILKSCREEN COLOR:" at 10494.94,2770.87 h60
  text "X" at 11442.67,2770.87 h60
  text "WHITE" at 11569.71,2770.87 h60
  text "OTHER" at 12080.71,2770.87 h60
  text "SOLDER RESIST COLOR:" at 10494.94,2600.87 h60
  text "X" at 12167.68,2446.67 h60
  text "GREEN" at 11189.71,2441.67 h60
  text "BLUE" at 11780.71,2441.67 h60
  text "OTHER" at 12318.71,2441.67 h60
  text "RED" at 12708.71,2436.67 h60
  text "IMMERSION GOLD (ENIG)" at 11400.71,2253.15 h60
  text "ENEPIG" at 12738.25,2249.87 h60
  text "SURFACE FINISH:" at 10339.71,2248.87 h60
  text "X" at 11213.77,2248.87 h60
  text "IMM. TIN/SILVER OR EQUIV" at 10669.25,2091.87 h60
  text "OTHER" at 12100.71,2091.87 h60
  text "ARRAY/PANEL:" at 10339.71,1912.87 h60
  text "CUT AND TRIM PER MECH LAYER 1" at 11400.72,1908.58 h60
  text "N.C. ROUTE" at 11400.71,1756.87 h60
  text "X" at 12079.71,1756.87 h60
  text "V. SCORE" at 12266.71,1756.87 h60
  text "CERTIFICATION:" at 10339.71,1619.87 h60
  text "MATERIALS AND WORKMANSHIP FOR ALL PCBS" at 11064.71,1619.87 h60
  text "TO MEET OR EXCEED THE REQUIREMENTS OF:" at 11064.71,1521.87 h60
  text "X" at 10691.22,1385.36 h60
  text "ANSI IPC-A-600F CLASS ->" at 10830.22,1385.36 h60
  text "X" at 12469.27,1385.36 h60
  text "2" at 12588.22,1385.36 h60
  text "1" at 12273.22,1383.87 h60
  text "3" at 12942.22,1383.87 h60
  text "X" at 10693.27,1225.87 h60
  text "UL 94V-0" at 10830.22,1225.87 h60
  text "X" at 11505.27,1225.87 h60
  text "RoHS" at 11642.22,1225.87 h60
  text "OTHER" at 12286.62,1225.87 h60
  text "PER ORDER" at 12683.68,1225.87 h60
  text "ADDITIONAL REQUIREMENTS:" at 10339.71,1084.87 h60
  text "X" at 12321.27,985.87 h60
  text "YES" at 12457.22,983.87 h60
  text "NO" at 12911.22,983.87 h60
  text "VIA TENTING:" at 11561.79,978.79 h60
  text "MICROSECTION:" at 10414.48,969.87 h60
  text "YES" at 11320.22,969.87 h60
  text "REQUIRED" at 12181.71,813.72 h60
  text "BARE BOARD ELEC. TEST:" at 10414.48,810.87 h60
  text "NONE" at 11720.22,810.87 h60
  text "X" at 12054.71,810.87 h60
  text "PER ORDER" at 12773.71,810.87 h60
  text "MANUFACTURER'S UL:" at 10414.48,653.87 h60
  text "RAIL" at 11580.22,649.58 h60
  text "METAL" at 12072.03,649.58 h60
  text "SILK" at 12583.71,649.58 h60
  text "X" at 12447.25,649.23 h60
  text "FAB NOTES" at -461.93,-1152.91 h60
M11 Gerber Information:
  lines w10: -1284.75,-1230.94 5315.25,-1230.94 ; -1284.75,-1027.6 5317.25,-1027.6 ; -1284.75,-824.27 -1284.75,-1434.27 2720.25,-1434.27 5317.25,-1434.27 5317.25,-824.27 -1284.25,-824.27 -1284.25,-1434.27 291.25,-1434.27 ; 1180.25,-1434.27 1180.25,-824.27 ; 2447.25,-1027.6 2447.25,-824.27 ; 3287.25,-1027.6 3287.25,-824.27 ; 3909.25,-1440.77 3909.25,-1237.94
  text "ALL ARTWORK VIEWED FROM TOP SIDE" at -1221.25,-956.44 h35
  text "BOARD #:" at 1255.25,-956.44 h35
  text ".PRJ_Number" at 1800.75,-956.44 h35
  text "REV:" at 2645.25,-956.44 h35
  text ".PCB_Rev" at 2936.75,-956.44 h35
  text "SVN REV:" at 3483.25,-956.44 h35
  text ".VersionControl_RevNumber" at 3989.25,-956.44 h35
  text "LAYER NAME =" at -1221.25,-1159.26 h35
  text "GENERATED    :" at 1257.25,-1365.11 h35
  text ".Print_Date" at 2126.75,-1365.11 h35
  text ".Print_Time" at 2855.75,-1365.11 h35
  text "TEXAS INSTRUMENTS" at 4120.25,-1365.11 h35
M12 Stackup:
  drawing of 296 lines, arcs and shapes, not listed
  text "LAYER STACK-UP :" at 4248.19,5847.83 h100
  text "Layer" at 4252.11,5694.9 h60
  text "Name" at 4662.02,5694.9 h60
  text "Material" at 5791.7,5694.9 h60
  text "Thickness" at 6651.47,5694.9 h60
  text "Constant" at 7301.3,5694.9 h60
  text "Board Layer Stack" at 7871.16,5694.9 h60
  text "1" at 4252.11,5574.9 h60
  text "SILKSCREEN TOP" at 4662.02,5574.9 h60
  text "2" at 4252.11,5454.9 h60
  text "Top Solder" at 4662.02,5454.9 h60
  text "Solder Resist" at 5791.7,5454.9 h60
  text "0.40mil" at 6651.47,5454.9 h60
  text "3.5" at 7301.3,5454.9 h60
  text "3" at 4252.11,5334.9 h60
  text "TOP" at 4662.02,5334.9 h60
  text "Copper" at 5791.7,5334.9 h60
  text "1.40mil" at 6651.47,5334.9 h60
  text "4" at 4252.11,5214.9 h60
  text "Dielectric1" at 4662.02,5214.9 h60
  text "FR-4 High Tg" at 5791.7,5214.9 h60
  text "16.00mil" at 6651.47,5214.9 h60
  text "4.5" at 7301.3,5214.9 h60
  text "5" at 4252.11,5094.9 h60
  text "GND" at 4662.02,5094.9 h60
  text "Copper" at 5791.7,5094.9 h60
  text "0.60mil" at 6651.47,5094.9 h60
  text "6" at 4252.11,4974.9 h60
  text "Dielectric2" at 4662.02,4974.9 h60
  text "FR-4 High Tg" at 5791.7,4974.9 h60
  text "26.00mil" at 6651.47,4974.9 h60
  text "4.5" at 7301.3,4974.9 h60
  text "7" at 4252.11,4854.9 h60
  text "PWR" at 4662.02,4854.9 h60
  text "Copper" at 5791.7,4854.9 h60
  text "0.60mil" at 6651.47,4854.9 h60
  text "8" at 4252.11,4734.9 h60
  text "Dielectric3" at 4662.02,4734.9 h60
  text "FR-4 High Tg" at 5791.7,4734.9 h60
  text "16.00mil" at 6651.47,4734.9 h60
  text "4.5" at 7301.3,4734.9 h60
  text "9" at 4252.11,4614.9 h60
  text "BOTTOM" at 4662.02,4614.9 h60
  text "Copper" at 5791.7,4614.9 h60
  text "1.40mil" at 6651.47,4614.9 h60
  text "10" at 4252.11,4494.9 h60
  text "Bottom Solder" at 4662.02,4494.9 h60
  text "Solder Resist" at 5791.7,4494.9 h60
  text "0.40mil" at 6651.47,4494.9 h60
  text "3.5" at 7301.3,4494.9 h60
  text "11" at 4252.11,4374.9 h60
  text "SILKSCREEN BOTTOM" at 4662.02,4374.9 h60
  text "THIS IS AN IMPEDANCE CONTROLLED BOARD." at 4680.5,4188.28 h100
  text "NOTE :" at 3800.85,4082.84 h80
  text "1. ALL CORE AND PREPREG THICKNESSES ARE UP TO FAB SHOP TO SELECT." at 3859.9,3955.51 h80
  text "2. EXTERNAL LAYER CU THICKNESSES ARE FINISHED THICKNESS AFTER PLATING." at 3859.9,3807.39 h80
  text "STACKUP" at -460.12,-1152.91 h60
Drill Drawing:
  circle w10: c2889.73,92.19 r30.56
  rectangle: -992.75,-575.77 -867.75,-450.77
  rectangle: -867.75,-700.77 -492.75,-575.77
  lines w7: -992.75,-575.77 7.25,-575.77 ; -867.75,-700.77 -867.75,-450.77 ; -742.75,-700.77 -742.75,-450.77 ; -492.75,-700.77 -492.75,-450.77 ; -242.75,-700.77 -242.75,-450.77 ; -992.75,-700.77 -992.75,-450.77 7.25,-450.77 7.25,-700.77 -992.75,-700.77
  lines w10: 3348.28,2198.06 4597.2,2198.06 ; 2859.18,1849.14 2920.29,1849.14 2920.29,1910.25 2859.18,1910.25 2859.18,1849.14
  lines w15: 2804.11,-117.11 9316.15,-117.11 ; 2804.11,1945.39 9316.15,1945.39 ; 3311.74,-254.61 3311.74,2082.89 ; 3863.26,-254.61 3863.26,2082.89 ; 4909.63,-254.61 4909.63,2082.89 ; 5376.01,-254.61 5376.01,2082.89 ; 6051.33,-254.61 6051.33,2082.89 ; 7033.55,-254.61 7033.55,2082.89 ; 8280.68,-254.61 8280.68,2082.89 ; 2804.11,-254.61 9316.15,-254.61 9316.15,2082.89 2804.11,2082.89 2804.11,-254.61
  text "DRILL CHART :" at 3350.86,2264.28 h100
  text "Symbol" at 2886.61,1986.64 h66
  text "Count" at 3352.99,1986.64 h66
  text "Hole Size" at 3904.51,1986.64 h66
  text "Plated" at 4950.88,1986.64 h66
  text "Hole Type" at 5417.26,1986.64 h66
  text "Hole Length" at 6092.58,1986.64 h66
  text "Routed Path Length" at 7074.8,1986.64 h66
  text "Hole Tolerance" at 8321.93,1986.64 h66
  text "36" at 3352.99,1849.14 h55
  text "7.87mil (0.200mm)" at 3904.51,1849.14 h55
  text "PTH" at 4950.88,1849.14 h55
  text "Round" at 5417.26,1849.14 h55
  text "-" at 6092.58,1849.14 h55
  text "-" at 7074.8,1849.14 h55
  text "4" at 3352.99,1711.64 h55
  text "7.87mil (0.200mm)" at 3904.51,1711.64 h55
  text "PTH" at 4950.88,1711.64 h55
  text "Round" at 5417.26,1711.64 h55
  text "-" at 6092.58,1711.64 h55
  text "-" at 7074.8,1711.64 h55
  text "+0.00mil/-7.87mil" at 8321.93,1711.64 h55
  text "A" at 2859.37,1701.65 h61.11
  text "270" at 3352.99,1574.14 h55
  text "8.00mil (0.203mm)" at 3904.51,1574.14 h55
  text "PTH" at 4950.88,1574.14 h55
  text "Round" at 5417.26,1574.14 h55
  text "-" at 6092.58,1574.14 h55
  text "-" at 7074.8,1574.14 h55
  text "+0.00mil/-4.00mil" at 8321.93,1574.14 h55
  text "B" at 2859.37,1564.15 h61.11
  text "142" at 3352.99,1436.64 h55
  text "12.00mil (0.305mm)" at 3904.51,1436.64 h55
  text "PTH" at 4950.88,1436.64 h55
  text "Round" at 5417.26,1436.64 h55
  text "-" at 6092.58,1436.64 h55
  text "-" at 7074.8,1436.64 h55
  text "+0.00mil/-4.00mil" at 8321.93,1436.64 h55
  text "C" at 2859.37,1426.65 h61.11
  text "23" at 3352.99,1299.14 h55
  text "15.00mil (0.381mm)" at 3904.51,1299.14 h55
  text "PTH" at 4950.88,1299.14 h55
  text "Round" at 5417.26,1299.14 h55
  text "-" at 6092.58,1299.14 h55
  text "-" at 7074.8,1299.14 h55
  text "+0.00mil/-4.00mil" at 8321.93,1299.14 h55
  text "D" at 2859.37,1289.15 h61.11
  text "2" at 3352.99,1161.64 h55
  text "23.62mil (0.600mm)" at 3904.51,1161.64 h55
  text "PTH" at 4950.88,1161.64 h55
  text "Slot" at 5417.26,1161.64 h55
  text "51.18mil (1.300mm)" at 6092.58,1161.64 h55
  text "27.56mil (0.700mm)" at 7074.8,1161.64 h55
  text "+/-3.00mil" at 8321.93,1161.64 h55
  text "E" at 2859.37,1151.65 h61.11
  text "20" at 3352.99,1024.14 h55
  text "27.95mil (0.710mm)" at 3904.51,1024.14 h55
  text "PTH" at 4950.88,1024.14 h55
  text "Round" at 5417.26,1024.14 h55
  text "-" at 6092.58,1024.14 h55
  text "-" at 7074.8,1024.14 h55
  text "+/-3.00mil" at 8321.93,1024.14 h55
  text "F" at 2859.37,1014.15 h61.11
  text "1" at 3352.99,886.64 h55
  text "37.99mil (0.965mm)" at 3904.51,886.64 h55
  text "PTH" at 4950.88,886.64 h55
  text "Round" at 5417.26,886.64 h55
  text "-" at 6092.58,886.64 h55
  text "-" at 7074.8,886.64 h55
  text "+/-3.00mil" at 8321.93,886.64 h55
  text "H" at 2859.37,876.65 h61.11
  text "6" at 3352.99,749.14 h55
  text "39.00mil (0.991mm)" at 3904.51,749.14 h55
  text "NPTH" at 4950.88,749.14 h55
  text "Round" at 5417.26,749.14 h55
  text "-" at 6092.58,749.14 h55
  text "-" at 7074.8,749.14 h55
  text "+/-2.00mil" at 8321.93,749.14 h55
  text "I" at 2869.55,739.15 h61.11
  text "6" at 3352.99,611.64 h55
  text "40.00mil (1.016mm)" at 3904.51,611.64 h55
  text "PTH" at 4950.88,611.64 h55
  text "Round" at 5417.26,611.64 h55
  text "-" at 6092.58,611.64 h55
  text "-" at 7074.8,611.64 h55
  text "+/-3.00mil" at 8321.93,611.64 h55
  text "K" at 2859.37,601.65 h61.11
  text "40" at 3352.99,474.14 h55
  text "40.16mil (1.020mm)" at 3904.51,474.14 h55
  text "PTH" at 4950.88,474.14 h55
  text "Round" at 5417.26,474.14 h55
  text "-" at 6092.58,474.14 h55
  text "-" at 7074.8,474.14 h55
  text "+/-3.00mil" at 8321.93,474.14 h55
  text "L" at 2859.37,464.15 h61.11
  text "8" at 3352.99,336.64 h55
  text "43.31mil (1.100mm)" at 3904.51,336.64 h55
  text "PTH" at 4950.88,336.64 h55
  text "Round" at 5417.26,336.64 h55
  text "-" at 6092.58,336.64 h55
  text "-" at 7074.8,336.64 h55
  text "+/-3.00mil" at 8321.93,336.64 h55
  text "M" at 2859.37,326.65 h61.11
  text "43" at 3352.99,199.14 h55
  text "45.28mil (1.150mm)" at 3904.51,199.14 h55
  text "PTH" at 4950.88,199.14 h55
  text "Round" at 5417.26,199.14 h55
  text "-" at 6092.58,199.14 h55
  text "-" at 7074.8,199.14 h55
  text "+/-3.00mil" at 8321.93,199.14 h55
  text "N" at 2859.37,189.15 h61.11
  text "4" at 3352.99,61.64 h55
  text "118.11mil (3.000mm)" at 3904.51,61.64 h55
  text "NPTH" at 4950.88,61.64 h55
  text "Round" at 5417.26,61.64 h55
  text "-" at 6092.58,61.64 h55
  text "-" at 7074.8,61.64 h55
  text "+/-0.00mil" at 8321.93,61.64 h55
  text "4" at 3352.99,-75.86 h55
  text "125.00mil (3.175mm)" at 3904.51,-75.86 h55
  text "NPTH" at 4950.88,-75.86 h55
  text "Round" at 5417.26,-75.86 h55
  text "-" at 6092.58,-75.86 h55
  text "-" at 7074.8,-75.86 h55
  text "+/-2.00mil" at 8321.93,-75.86 h55
  text "O" at 2859.37,-85.85 h61.11
  text "609 Total" at 3352.99,-213.36 h55
  text "Slot definitions :" at 2886.61,-347.92 h55
  text "Routed Path Length" at 3835.57,-347.92 h55
  text "= Calculated from tool start centre position to tool end centre position." at 4848.68,-347.92 h55
  text "Hole Length" at 3835.57,-441.23 h55
  text "= Routed Path Length + Tool Size = Slot length as defined in the PCB layout" at 4472.97,-441.23 h55
  text "FAB" at -467.21,-1136.22 h60

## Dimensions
1287.93,-164.4 to 2200.85,-275.07 on M2 Board Dimensions
2211.78,136.9 to 2238.93,-99.87 on M2 Board Dimensions
2271.27,2017.26 to 2120.79,-100.74 on M2 Board Dimensions
2200.43,2605.23 to 2200.46,2490.05 on M2 Board Dimensions
-992.75,-700.77 to 7.25,-700.77 on Drill Drawing
12.88,-15.85 to 133.56,-231.92 on M2 Board Dimensions
2200.79,-20.74 to 0,0 on M2 Board Dimensions
0,0 to -99.21,-20.74 on M2 Board Dimensions
0,0 to -19.21,-100.74 on M2 Board Dimensions
0,0 to -19.21,4179.26 on M2 Board Dimensions
2200.72,2489.82 to 2200.79,2294.45 on M2 Board Dimensions
2168.11,-123.36 to 2105.14,-182.77 on M2 Board Dimensions
-110.92,2142.89 to -156.91,2205.17 on M2 Board Dimensions
-99.21,4099.26 to 197.88,4179.26 on M2 Board Dimensions
338.94,4332.46 to 350.27,4425.26 on M2 Board Dimensions
459.69,4179.26 to 690.13,4179.26 on M2 Board Dimensions
2200.79,2294.45 to 2200.79,2017.26 on M2 Board Dimensions
2163.79,4249.6 to 967.31,4179.26 on M2 Board Dimensions
328.62,5241.11 to 247,5167.73 on M2 Board Dimensions
388.99,5362.14 to 501.19,5362.14 on M2 Board Dimensions
333.87,5269.62 to 333.87,5342.46 on M2 Board Dimensions
556.31,5342.46 to 576,5362.14 on M2 Board Dimensions
556.31,5269.62 to 576,5362.14 on M2 Board Dimensions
